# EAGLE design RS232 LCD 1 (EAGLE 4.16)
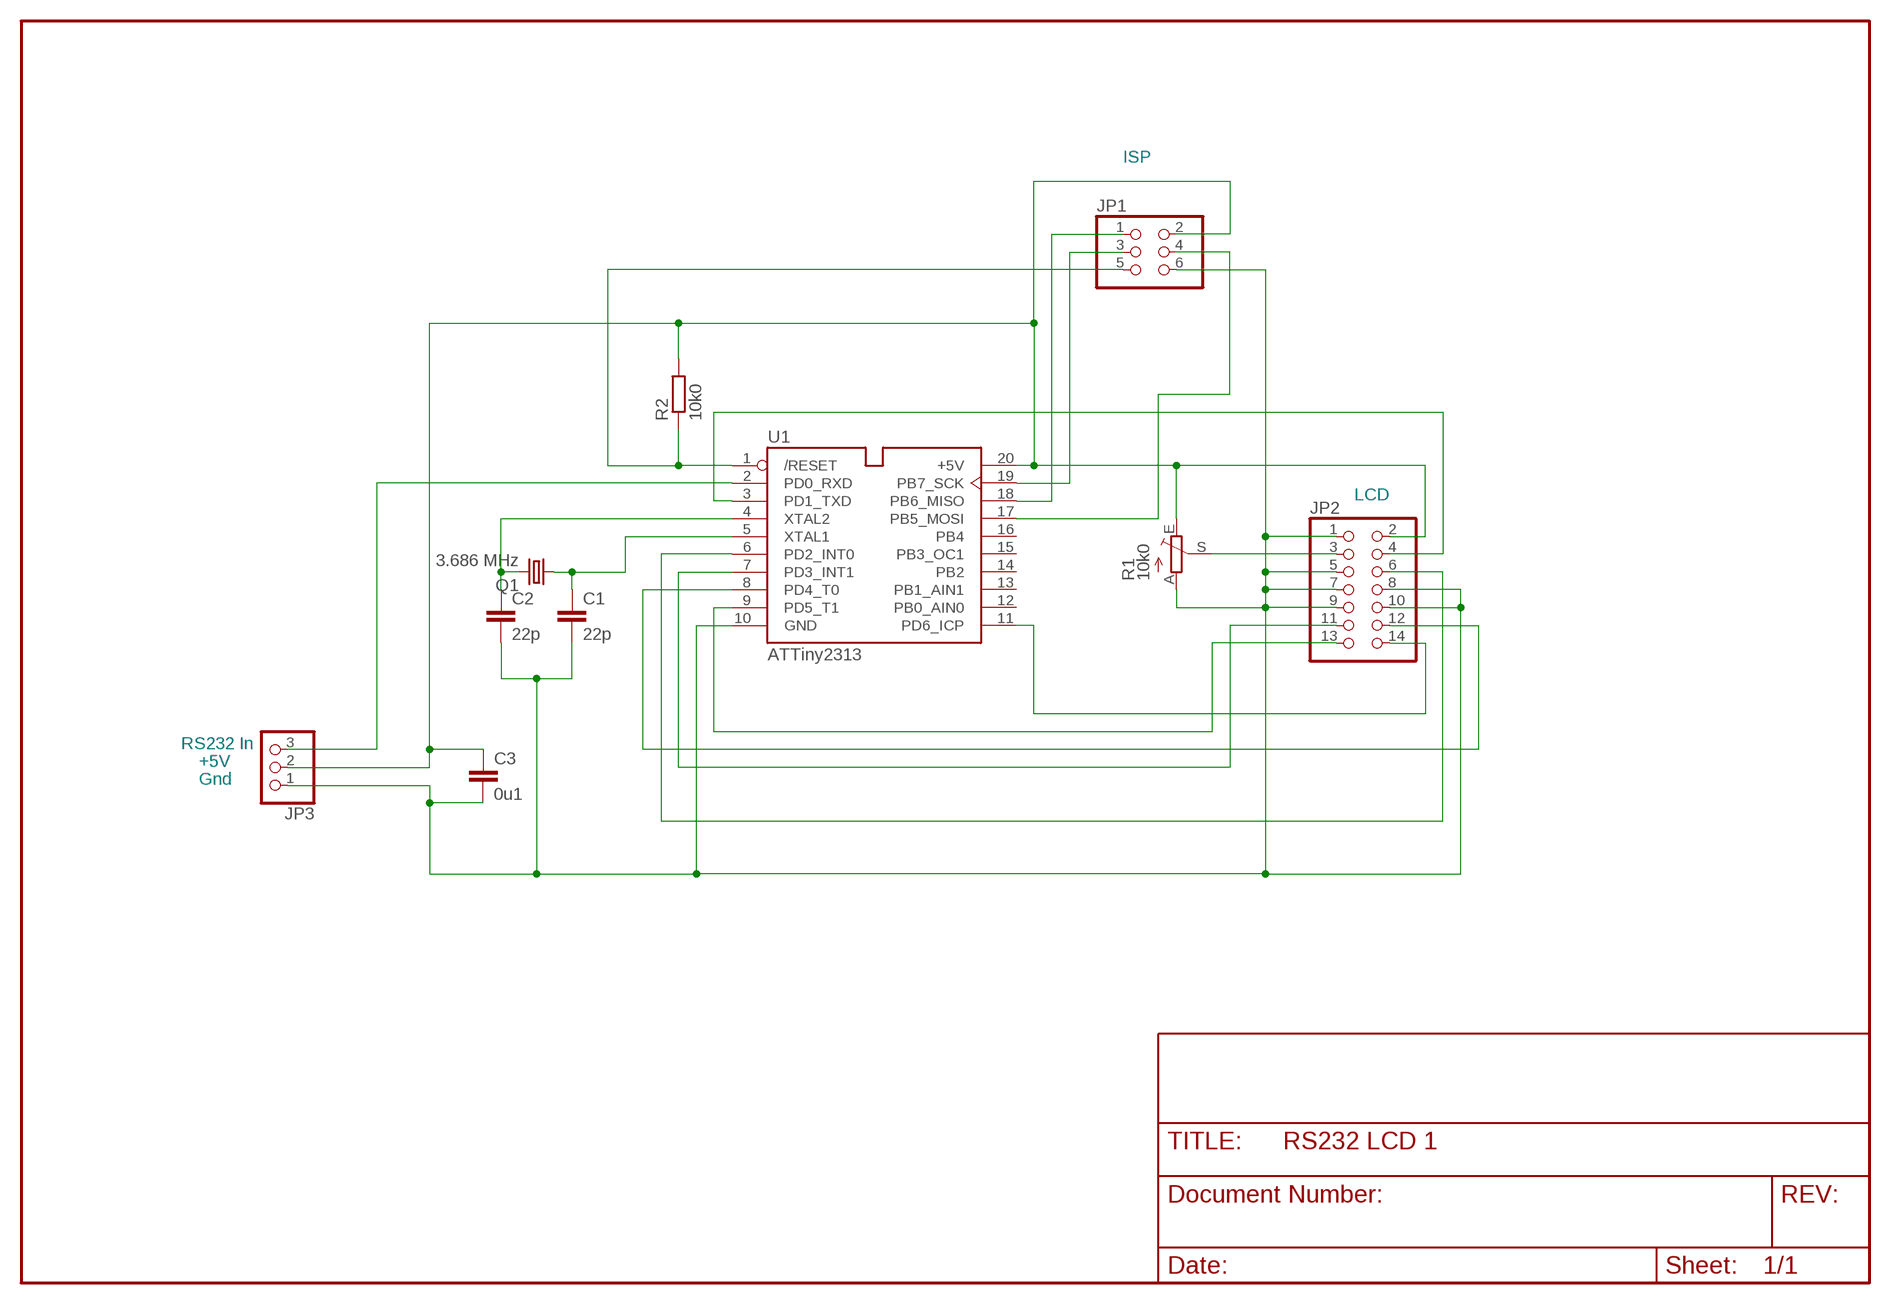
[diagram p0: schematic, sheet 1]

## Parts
C1  22p  C-EU050-025X075  [C050-025X075]
C2  22p  C-EU050-025X075  [C050-025X075]
C3  0u1  C-EU025-030X050  [C025-030X050]
JP1  PINHD-2X3  [2X03]
JP2  PINHD-2X7  [2X07]
JP3  PINHD-1X3  [1X03]
Q1  3.686 MHz  CRYSTALHC18U-V  [HC18U-V]
R1  10k0  TRIM_EU-PT10  [PT-10]
R2  10k0  R-EU_0207/10  [0207/10]
U1  ATTiny2313  AT90S2313_SO-20  [SO-20]

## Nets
+5V [Power]: C3.1 JP1.2 JP2.2 JP3.2 R1.E R2.2 U1.20(+5V)
CONTR: JP2.3 R1.S
D4: JP2.11 U1.7(PD3_INT1)
D5: JP2.12 U1.8(PD4_T0)
D6: JP2.13 U1.9(PD5_T1)
D7: JP2.14 U1.11(PD6_ICP)
E: JP2.6 U1.6(PD2_INT0)
GND [Power]: C1.2 C2.2 C3.2 JP1.6 JP2.1 JP2.5 JP2.7 JP2.8 JP2.9 JP2.10 JP3.1 R1.A U1.10(GND)
MISO: JP1.1 U1.18(PB6_MISO)
MOSI: JP1.4 U1.17(PB5_MOSI)
R/S: JP2.4 U1.3(PD1_TXD)
RST: JP1.5 R2.1 U1.1(/RESET)
RXD: JP3.3 U1.2(PD0_RXD)
SCK: JP1.3 U1.19(PB7_SCK)
XTAL1: C1.1 Q1.1 U1.5(XTAL1)
XTAL2: C2.1 Q1.2 U1.4(XTAL2)
Unconnected: U1.12(PB0_AIN0) U1.13(PB1_AIN1) U1.14(PB2) U1.15(PB3_OC1) U1.16(PB4)

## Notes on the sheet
- ISP
- LCD
- RS232 In
- +5V
- Gnd

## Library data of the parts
C1-C3 = rcl:C-EU: CAPACITOR, European symbol
JP1 = pinhead:PINHD-2X3: PIN HEADER
JP2 = pinhead:PINHD-2X7: PIN HEADER
JP3 = pinhead:PINHD-1X3: PIN HEADER
Q1 = crystal:CRYSTAL: CRYSTAL
R1 = pot:TRIM_EU-: POTENTIOMETER
R2 = rcl:R-EU_: RESISTOR, European symbol
U1 = atmel_prototype_header:AT90S2313: 8-bit AVR Microcontroller with 2K bytes In-System Programmable Flash

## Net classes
0 default: width 0.254 mm
1 Power: width 0.635 mm

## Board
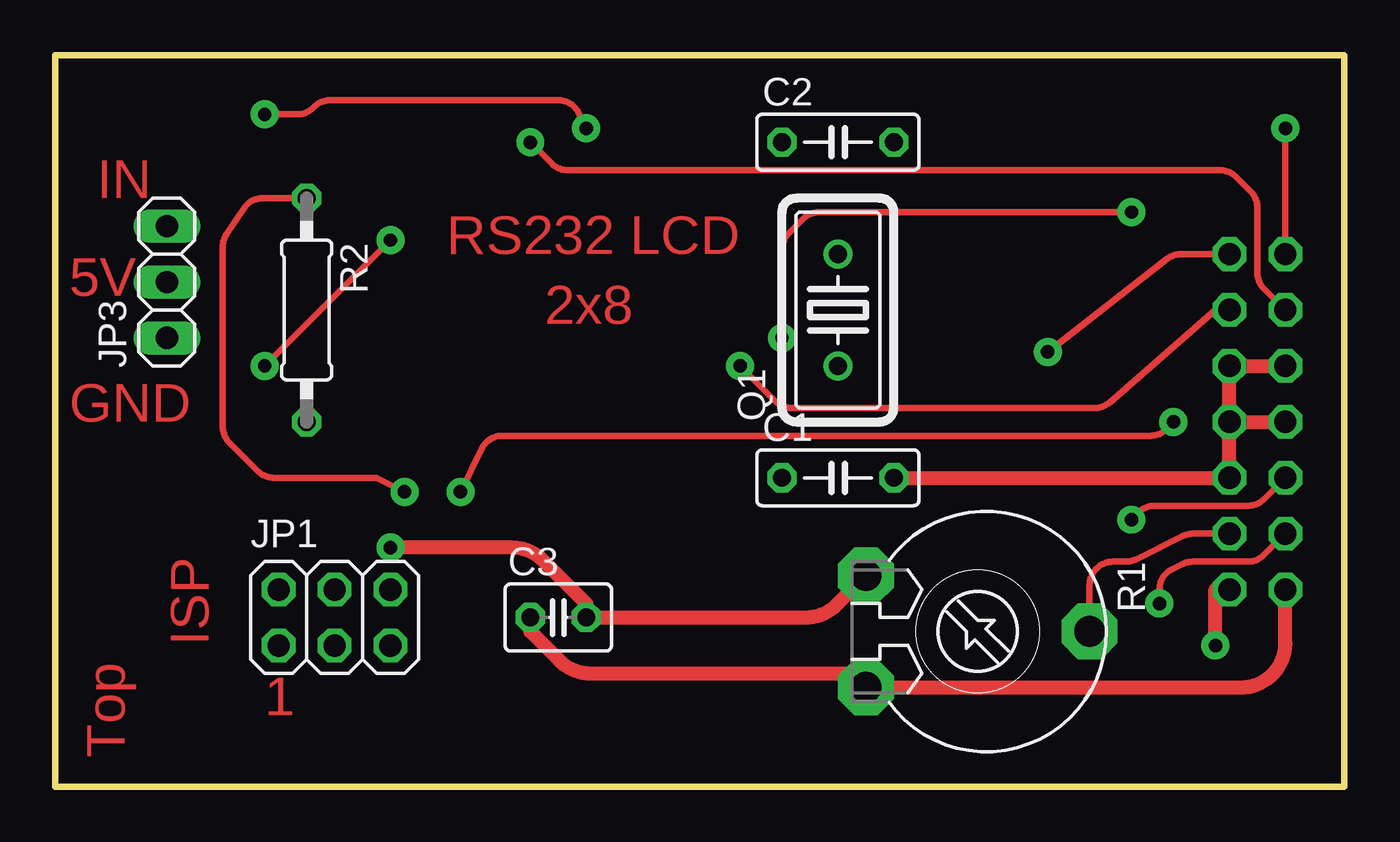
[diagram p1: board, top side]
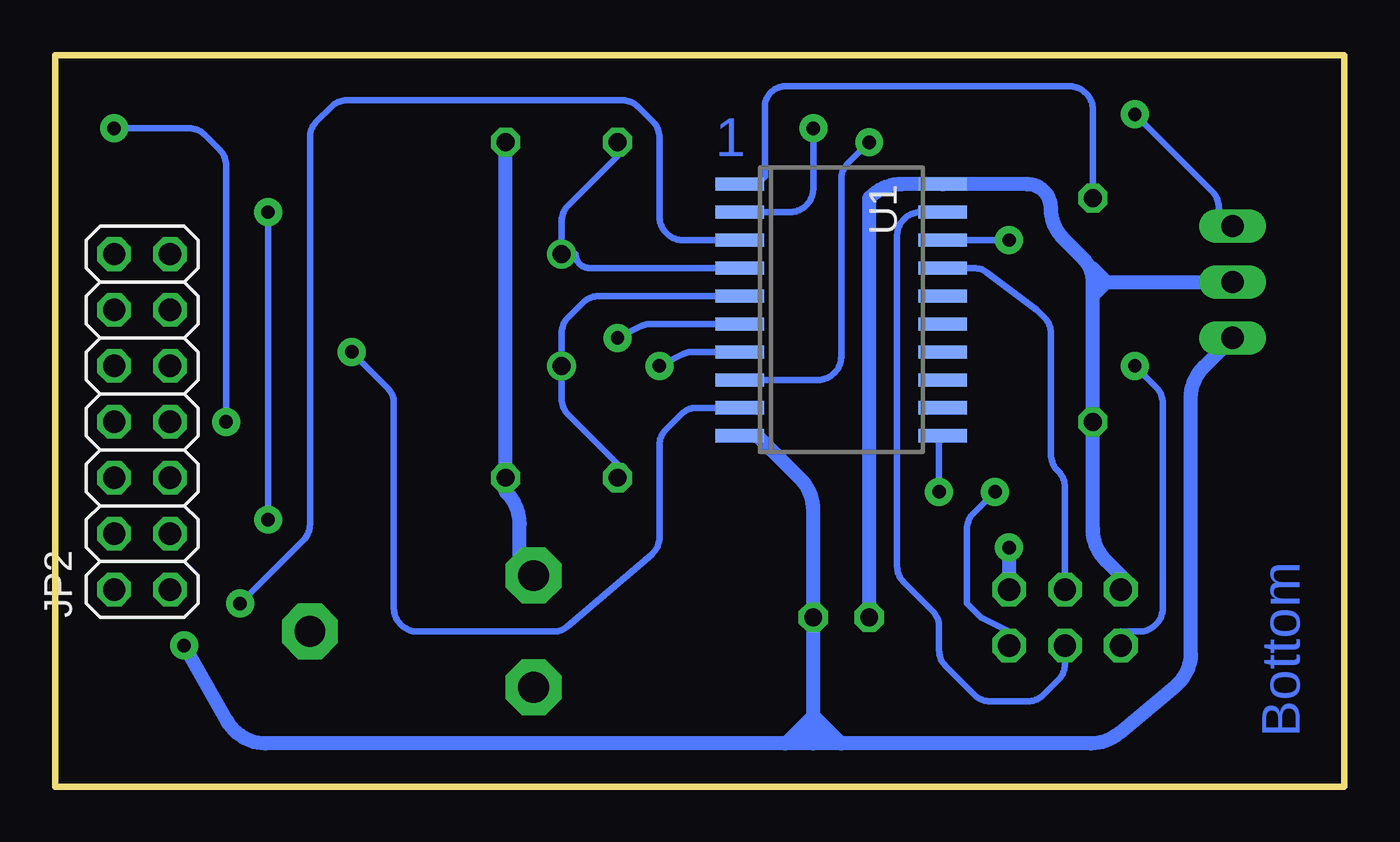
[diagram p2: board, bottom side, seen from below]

Size 58.56 x 33.24 mm. Coordinates in mm from the lower left corner, seen from the top.
Outline: 0,0 58.56,0 58.56,33.24 0,33.24 0,0
Copper layers (1*16): Top 0.035mm / dielectric 1.5mm / Bottom 0.035mm
Design rules "Doppelt_eigene_grosse_vias": minimum track width 12mil, minimum drill 24mil, track to track 15mil, track to pad 15mil, pad to pad 20mil, via to via 20mil, smd to smd 8mil, copper to edge 20mil, drill to drill 8mil, minimum pad ring 10mil, minimum via ring 13mil, stop-mask expansion 4mil, vias tented up to drill 0mil, thermal gap 10mil
tRestrict: area 33,22.9 to 38.1,25.5; area 33,17.9 to 38.1,20.4; area 3.8,19.1 to 6.3,26.7; area 8.9,5.2 to 16.5,10.2
bRestrict: area 52.1,7.7 to 57.1,25.5
vRestrict: area 20.3,15.3 to 25.4,28

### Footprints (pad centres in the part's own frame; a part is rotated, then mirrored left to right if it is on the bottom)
C050-025X075 = drill 0.813 octagon: 1 -2.54,0; 2 2.54,0
C025-030X050 = drill 0.813 octagon: 1 -1.27,0; 2 1.27,0
2X03 = drill 1.016 octagon: 1 -2.54,-1.27; 2 -2.54,1.27; 3 0,-1.27; 4 0,1.27; 5 2.54,-1.27; 6 2.54,1.27
2X07 = drill 1.016 octagon: 1 -7.62,-1.27; 2 -7.62,1.27; 3 -5.08,-1.27; 4 -5.08,1.27; 5 -2.54,-1.27; 6 -2.54,1.27; 7 0,-1.27; 8 0,1.27; 9 2.54,-1.27; 10 2.54,1.27; 11 5.08,-1.27; 12 5.08,1.27; 13 7.62,-1.27; 14 7.62,1.27
1X03 = drill 1.016 long: 1 -2.54,0; 2 0,0; 3 2.54,0
HC18U-V = drill 0.813 round: 1 -2.54,0; 2 2.54,0
PT-10 = drill 1.4 pad 2.54 octagon: A -2.54,-5.08; E 2.54,-5.08; S 0,5.08
0207/10 = drill 0.813 octagon: 1 -5.08,0; 2 5.08,0
SO-20 = smd 0.6 x 2.2: 1 -5.715,-4.6; 2 -4.445,-4.6; 3 -3.175,-4.6; 4 -1.905,-4.6; 5 -0.635,-4.6; 6 0.635,-4.6; 7 1.905,-4.6; 8 3.175,-4.6; 9 4.445,-4.6; 10 5.715,-4.6; 11 5.715,4.6; 12 4.445,4.6; 13 3.175,4.6; 14 1.905,4.6; 15 0.635,4.6; 16 -0.635,4.6; 17 -1.905,4.6; 18 -3.175,4.6; 19 -4.445,4.6; 20 -5.715,4.6

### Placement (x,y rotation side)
C1  35.56,14.04 0 top
C2  35.56,29.28 0 top
C3  22.86,7.69 0 top
JP1  12.7,7.69 0 top
JP2  54.61,16.58 90 bottom
JP3  5.08,22.93 90 top
Q1  35.56,21.66 90 top
R1  41.91,7.06 270 top
R2  11.42,21.66 270 top
U1  22.86,21.66 270 bottom

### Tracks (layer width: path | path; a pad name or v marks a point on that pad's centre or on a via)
+5V
  Top 0.635: C3.1 21.59,7.06 22.9,5.74 arc45 24.32,5.15 36.19,5.15 R1.E 53.88,4.52 arc90 55.88,6.52 JP2.2
  Bottom 0.61: 11.42,23.57 10.79,22.93 11.42,22.3
  Bottom 0.635: 11.42,22.93 arc-45 11.87,24.02 12.74,24.89 arc45 13.33,26.3 arc-90 14.41,27.38 U1.20 20.12,27.38 arc-45 21.54,26.79 arc-45 21.59,26.67 C3.1 | 11.42,22.93 11.42,22.3 R2.2 11.42,11.7 arc-45 10.84,10.28 10.16,9.6 JP1.2 | 11.42,22.93 10.79,22.93 JP3.2
CONTR
  Top 0.305: R1.S 46.98,9.18 arc-45 47.28,9.89 47.33,9.94 arc-45 48.03,10.23 48.65,10.23 arc27 49.1,10.34 51.22,11.4 arc-27 51.67,11.5 JP2.3
D4  (via drill 0.61)
  Top 0.305: v31.11,19.12 32.72,17.51 arc45 33.43,17.22 47.24,17.22 arc41 47.9,17.46 52.7,21.66 JP2.11
  Bottom 0.305: U1.7 29.6,19.76 arc-27 30.05,19.65 v31.11,19.12
D5  (via drill 0.61)
  Top 0.305: JP2.12 54.9,22.64 arc-45 54.61,23.35 54.61,26.33 arc45 54.31,27.04 53.63,27.72 arc45 52.92,28.01 23.27,28.01 arc-45 22.56,28.31 v21.59,29.28
  Bottom 0.305: v21.59,29.28 22.56,28.31 arc-45 22.86,27.6 22.86,19.54 arc45 23.15,18.83 23.2,18.78 arc45 23.9,18.49 U1.8
D6  (via drill 0.61)
  Top 0.305: v45.08,19.76 50.52,23.99 arc-38 51.14,24.2 JP2.13
  Bottom 0.305: v45.08,19.76 43.47,18.15 arc45 43.17,17.44 43.17,8.11 arc-45 42.88,7.4 42.83,7.35 arc-45 42.13,7.06 35.92,7.06 arc-41 35.27,7.3 31.46,10.57 arc-49 31.11,11.33 31.11,15.53 arc45 30.82,16.24 30.13,16.92 arc45 29.43,17.22 U1.9
D7  (via drill 0.61)
  Top 0.305: v18.41,13.41 19.4,15.39 arc-63 20.3,15.95 49.75,15.95 arc45 50.45,16.24 v50.8,16.58 | v55.88,29.92 JP2.14
  Bottom 0.305: v18.41,13.41 18.41,15.95 U1.11 | v50.8,16.58 50.8,28.23 arc-45 51.09,28.94 51.77,29.62 arc-45 52.48,29.92 v55.88,29.92
E  (via drill 0.61)
  Top 0.305: v33.02,20.39 33.02,24.42 arc-45 33.31,25.13 33.99,25.81 arc-45 34.7,26.11 v48.89,26.11 | v48.89,12.14 49.23,12.48 arc-45 49.94,12.77 54.19,12.77 arc45 54.9,13.07 JP2.6
  Bottom 0.305: U1.6 31.51,21.03 arc-27 31.96,20.92 v33.02,20.39 | v48.89,26.11 v48.89,12.14
GND  (via drill 0.61)
  Top 0.635: JP2.10 JP2.9 JP2.7 | JP2.7 JP2.5 C1.2 | JP2.7 JP2.8 | v15.23,10.87 20.76,10.87 arc-45 22.17,10.28 24.12,8.33 C3.2 34.09,7.69 arc45 35.51,8.28 R1.A | v52.7,6.42 52.7,8.96 JP2.1
  Bottom 0.61: 23.49,2.61 24.12,3.25 24.76,2.61 | 22.86,1.98 23.49,2.61 | 24.76,2.61 25.39,1.98 | 23.49,2.61 24.76,2.61
  Bottom 0.635: R1.A 37.46,10.23 37.46,11.94 arc-45 38.05,13.36 38.09,13.41 C1.2 C2.2 | U1.10 26.67,15.95 24.71,13.99 arc45 24.12,12.58 C3.2 24.12,3.25 24.12,1.98 | v15.23,10.87 JP1.6 | 24.12,1.98 25.39,1.98 49,1.98 arc60 50.74,2.99 v52.7,6.42 | 24.12,1.98 22.86,1.98 11.51,1.98 arc-40 10.23,2.44 7.7,4.55 arc-50 6.98,6.09 6.98,17.66 arc45 6.39,19.07 JP3.1
MISO  (via drill 0.61)
  Top 0.305: v9.52,19.12 v15.23,24.84
  Bottom 0.305: v9.52,19.12 8.54,18.15 arc45 8.25,17.44 8.25,8.11 arc45 8.54,7.4 8.59,7.35 arc45 9.3,7.06 10.16,7.06 JP1.1 | v15.23,24.84 U1.18
MOSI
  Bottom 0.305: JP1.4 12.7,13.63 arc-45 12.99,14.34 13.04,14.38 arc45 13.33,15.09 13.33,20.61 arc-45 13.62,21.32 13.97,21.66 16.24,23.37 arc-37 16.84,23.57 U1.17
R/S  (via drill 0.61)
  Top 0.305: JP2.4 54.9,10.53 arc-45 54.19,10.23 51.67,10.23 arc27 51.22,10.13 50.71,9.87 arc63 50.16,8.98 v50.16,8.33
  Bottom 0.305: U1.3 30.06,24.84 arc45 30.77,25.13 30.82,25.18 arc45 31.11,25.89 31.11,29.5 arc-45 31.4,30.21 32.09,30.89 arc-45 32.79,31.19 45.3,31.19 arc-45 46.01,30.89 46.69,30.21 arc-45 46.98,29.5 46.98,11.92 arc45 47.28,11.21 v50.16,8.33
RST  (via drill 0.61)
  Top 0.305: v15.87,13.41 14.6,14.04 9.93,14.04 arc-45 9.23,14.34 7.91,15.65 arc-45 7.62,16.36 7.62,24.53 arc-34 7.78,25.09 8.59,26.3 arc-56 9.42,26.74 R2.1
  Bottom 0.305: U1.1 26.67,27.38 26.32,27.72 26.32,30.89 arc90 25.39,31.82 23.49,31.82 | v15.87,13.41 16.85,12.43 arc-45 17.14,11.72 17.14,8.33 16.5,7.69 15.23,7.06 JP1.5 | R2.1 11.42,30.77 arc-45 11.72,31.48 11.77,31.53 arc-45 12.47,31.82 23.49,31.82 | 23.49,31.82 23.71,31.82
RXD  (via drill 0.61)
  Top 0.305: v9.52,30.55 11.01,30.55 arc45 11.72,30.85 11.77,30.89 arc-45 12.47,31.19 22.87,31.19 arc-63 23.77,30.63 v24.12,29.92
  Bottom 0.305: v9.52,30.55 6,27.04 arc45 5.71,26.33 5.71,26.11 JP3.3 | v24.12,29.92 24.12,27.16 arc45 24.42,26.45 24.47,26.4 arc45 25.17,26.11 U1.2
SCK
  Bottom 0.305: U1.19 19.27,26.11 arc-45 19.97,25.81 20.02,25.77 arc-45 20.31,25.06 20.31,10.01 arc-45 20.02,9.3 18.7,7.99 arc45 18.41,7.28 18.41,6.2 arc-45 18.12,5.49 16.8,4.18 arc-45 16.09,3.88 14.38,3.88 arc-45 13.67,4.18 12.99,4.86 arc-45 12.7,5.57 JP1.3
XTAL1
  Bottom 0.305: U1.5 33.87,22.3 arc-45 34.58,22 35.26,21.32 arc-45 35.56,20.61 Q1.1 35.56,17.63 arc-45 35.26,16.92 33.02,14.68 C1.1
XTAL2
  Bottom 0.305: U1.4 34.28,23.57 arc90 34.92,24.2 Q1.2 35.56,25.69 arc45 35.26,26.4 33.02,28.65 C2.1

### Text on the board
Top: IN | RS232 LCD | 5V | 2x8 | GND | ISP | 1 | Top
Bottom: 1 | Bottom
